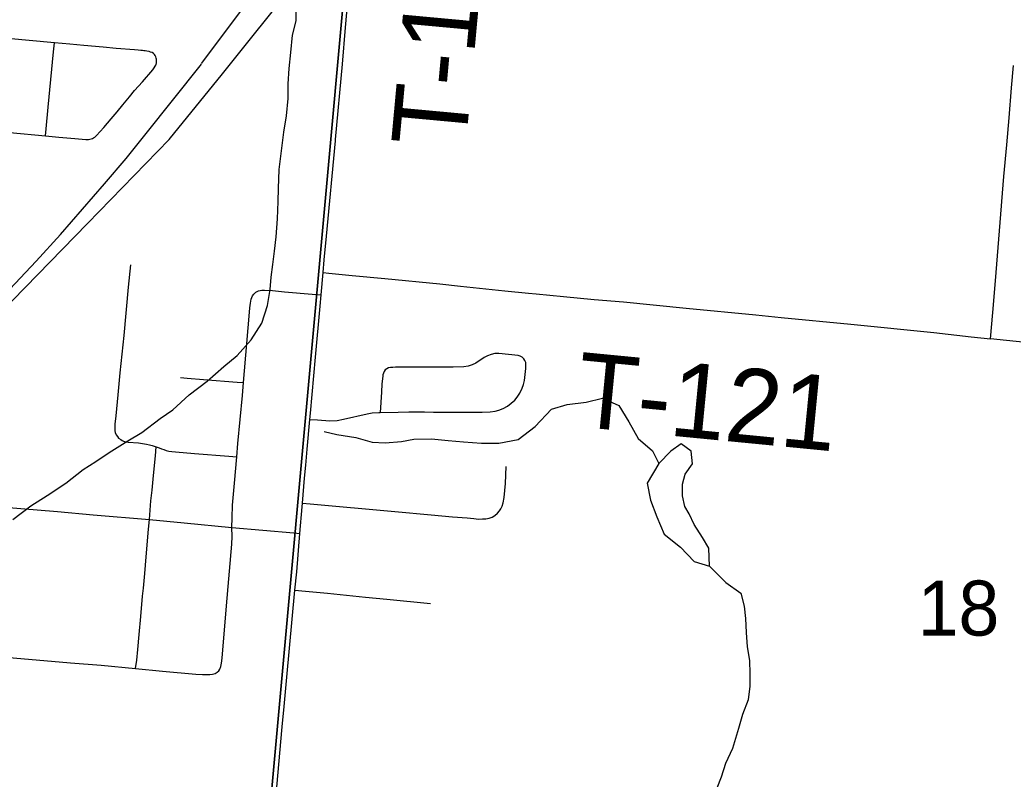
# Model space of a CAD drawing. Extents: x 0 to 1067, y 0 to 440.
# Drawn here: x 802.528 to 803.284, y 352.724 to 353.302 of the extents above; entities that cross this region are included whole.
import ezdxf

# ---------------------------------------------------------------- set-up
doc = ezdxf.new("R2010")
doc.units = 0
for name, color, linetype in [('GM_X_City_Street', 7, 'Continuous'), ('GM_X_Minor_Lake', 7, 'Continuous'), ('GM_X_Minor_River', 7, 'Continuous'), ('GM_X_Rail_Line', 7, 'Continuous'), ('GM_X_Section', 7, 'Continuous'), ('GM_X_Section_Text', 7, 'Continuous'), ('GM_X_Township_Road', 7, 'Continuous'), ('GM_X_Township_Road_Text', 7, 'Continuous')]:
    doc.layers.add(name, color=color, linetype=linetype)

msp = doc.modelspace()

# ---------------------------------------------------------------- linework, layer by layer
at = {"layer": 'GM_X_City_Street'}
for points in [[(802.49288, 353.21865), (802.54739, 353.21361), (802.55772, 353.21269), (802.56973, 353.21163), (802.57809, 353.21089), (802.57915, 353.21087), (802.58015, 353.21087), (802.58119, 353.21098), (802.58224, 353.21123), (802.58316, 353.21158), (802.58411, 353.21207), (802.58493, 353.21263), (802.58576, 353.21334), (802.5864, 353.21397), (802.59183, 353.22005), (802.59756, 353.22656), (802.60194, 353.23187), (802.60631, 353.23713), (802.61145, 353.24331), (802.61534, 353.24812), (802.62121, 353.25481), (802.62921, 353.26394), (802.63024, 353.26545), (802.63101, 353.26666), (802.63137, 353.26732), (802.63161, 353.26792), (802.6319, 353.26919), (802.63202, 353.27026), (802.63201, 353.27133), (802.63193, 353.27207), (802.63177, 353.27284), (802.6315, 353.27379), (802.63107, 353.27471), (802.63052, 353.27554), (802.62963, 353.27633), (802.62858, 353.27695), (802.62754, 353.27738), (802.62637, 353.27771), (802.62471, 353.27808), (802.62347, 353.2783), (802.62243, 353.27843), (802.6214, 353.27857), (802.62, 353.2787), (802.61802, 353.27886), (802.61527, 353.27908), (802.60137, 353.28023), (802.59148, 353.2811), (802.5766, 353.28241), (802.5661, 353.28333), (802.55427, 353.28439), (802.51845, 353.28759)], [(802.54739, 353.21361), (802.54788, 353.21889), (802.54944, 353.23552), (802.55349, 353.27746), (802.55427, 353.28439)], [(802.61215, 353.11542), (802.61053, 353.09856), (802.60699, 353.0616), (802.60409, 353.03321), (802.60256, 353.0165), (802.60095, 353.00048), (802.60035, 352.99415), (802.6002, 352.9918), (802.6002, 352.99014), (802.60027, 352.989), (802.6005, 352.98779), (802.60118, 352.98612), (802.60218, 352.98468), (802.60312, 352.98362), (802.60472, 352.9824), (802.6058, 352.98174), (802.60693, 352.98121), (802.60837, 352.98083), (802.61033, 352.98053), (802.6182, 352.97992), (802.62131, 352.97947), (802.62433, 352.97894), (802.62668, 352.97841), (802.62865, 352.97788), (802.6318, 352.97693), (802.63394, 352.97621), (802.63591, 352.97546), (802.63765, 352.97478), (802.63939, 352.97417), (802.64125, 352.97367), (802.64363, 352.97334), (802.64635, 352.97311), (802.6608, 352.9719), (802.68705, 352.96971), (802.69308, 352.9692)], [(802.67809, 352.80532), (802.67932, 352.80641), (802.68019, 352.80778), (802.68095, 352.80966), (802.68148, 352.8122), (802.68195, 352.81594), (802.6854, 352.85588), (802.68928, 352.90292), (802.68955, 352.90879), (802.68942, 352.91548), (802.68955, 352.92299), (802.68994, 352.93261), (802.69129, 352.94926), (802.69308, 352.9692), (802.694, 352.97953), (802.69739, 353.01605), (802.69823, 353.02588), (802.70252, 353.07629), (802.70312, 353.08283), (802.70361, 353.08639), (802.70416, 353.0894), (802.70509, 353.09186), (802.70605, 353.09317), (802.70771, 353.09471), (802.70976, 353.09567), (802.71207, 353.09605), (802.7143, 353.09618), (802.7204, 353.09587), (802.72945, 353.09496), (802.75049, 353.09321), (802.75738, 353.09273)], [(802.74875, 352.99781), (802.75469, 352.99738), (802.76405, 352.9967), (802.76946, 352.99696), (802.77426, 352.9979), (802.79244, 353.00209), (802.79616, 353.00271), (802.80116, 353.00306), (802.80226, 353.00307), (802.8161, 353.00325), (802.82415, 353.00355), (802.83599, 353.00355), (802.8428, 353.00332), (802.88001, 353.00326), (802.88614, 353.00352), (802.88972, 353.00405), (802.89261, 353.00483), (802.89596, 353.00617), (802.89911, 353.0079), (802.90201, 353.01005), (802.90468, 353.0125), (802.9066, 353.01477), (802.90858, 353.01779), (802.91048, 353.02157), (802.91149, 353.02438), (802.91215, 353.0273), (802.91316, 353.03647), (802.91329, 353.03946), (802.91307, 353.04113), (802.9125, 353.04266), (802.91158, 353.04398), (802.91035, 353.04507), (802.90891, 353.0459), (802.90732, 353.04637), (802.90002, 353.04729), (802.89266, 353.04794), (802.88968, 353.04786), (802.88681, 353.04731), (802.88404, 353.04628), (802.88143, 353.04484), (802.87522, 353.04067), (802.87231, 353.03925), (802.86922, 353.03827), (802.86604, 353.03777), (802.85788, 353.03751), (802.83925, 353.03764), (802.82999, 353.03758), (802.81942, 353.03752), (802.81391, 353.03745), (802.81204, 353.03734), (802.81012, 353.03725), (802.80869, 353.03696), (802.80725, 353.03629), (802.8062, 353.03552), (802.80524, 353.03428), (802.80476, 353.03304), (802.80441, 353.03171), (802.80429, 353.03083), (802.80359, 353.02479), (802.80321, 353.01859), (802.80226, 353.00307)], [(802.65015, 353.02958), (802.65533, 353.02922), (802.66766, 353.02821), (802.69332, 353.02625), (802.69823, 353.02588)], [(802.6161, 352.80812), (802.61689, 352.81451), (802.61766, 352.82262), (802.61882, 352.83414), (802.6201, 352.84771), (802.62144, 352.86333), (802.62199, 352.86936), (802.62301, 352.88044), (802.62408, 352.8933), (802.62597, 352.91431), (802.62653, 352.9215), (802.62719, 352.92863), (802.62773, 352.9358), (802.62858, 352.94389), (802.6295, 352.95223), (802.63049, 352.96274), (802.63118, 352.97013), (802.6318, 352.97693)], [(802.7431, 352.93396), (802.74909, 352.93342), (802.81334, 352.9276), (802.8412, 352.9252), (802.8573, 352.9237), (802.86846, 352.92279), (802.87347, 352.9223), (802.87704, 352.92193), (802.88026, 352.92199), (802.88271, 352.92212), (802.88514, 352.9226), (802.88745, 352.92348), (802.88959, 352.92475), (802.89149, 352.92635), (802.89312, 352.92822), (802.89417, 352.92977), (802.89523, 352.93166), (802.89597, 352.93417), (802.89662, 352.93845), (802.89759, 352.94897), (802.8983, 352.96198)], [(802.47619, 352.93422), (802.5005, 352.93214), (802.5566, 352.92763), (802.58364, 352.92526), (802.62653, 352.9215)], [(802.62653, 352.9215), (802.65311, 352.91917), (802.68942, 352.91548)], [(802.68942, 352.91548), (802.73652, 352.91139), (802.74116, 352.91099)], [(802.73739, 352.86781), (802.74543, 352.86704), (802.76213, 352.86545), (802.79119, 352.86255), (802.80728, 352.86096), (802.84071, 352.85769)], [(802.44711, 352.82277), (802.45292, 352.82227), (802.47893, 352.82006), (802.5664, 352.81247), (802.58989, 352.81065), (802.6161, 352.80812), (802.63661, 352.80614), (802.66205, 352.80392), (802.66701, 352.80366), (802.67255, 352.80375), (802.67454, 352.80396), (802.67672, 352.8045), (802.67809, 352.80532)]]:
    msp.add_lwpolyline(points, dxfattribs=at)
at = {"layer": 'GM_X_Minor_Lake'}
for points in [[(803.05313, 352.8862), (803.05244, 352.8999), (803.04759, 352.9079), (803.04124, 352.91781), (803.03752, 352.9258), (803.03416, 352.93152), (803.03234, 352.9395), (803.03241, 352.94859), (803.03437, 352.95616), (803.04011, 352.96408), (803.03905, 352.97357), (803.03153, 352.97931), (803.02354, 352.97369), (803.01438, 352.96428)], [(803.01438, 352.96428), (803.00556, 352.94918), (803.0081, 352.93627), (803.01291, 352.92372), (803.01848, 352.91041), (803.03088, 352.90045), (803.04139, 352.88975), (803.05313, 352.8862)]]:
    msp.add_lwpolyline(points, dxfattribs=at)
at = {"layer": 'GM_X_Minor_River'}
for points in [[(802.52257, 352.92152), (802.53628, 352.93203), (802.54882, 352.93989), (802.5629, 352.94926), (802.57623, 352.95977), (802.58574, 352.96576), (802.59601, 352.9725), (802.61008, 352.98149), (802.62073, 352.98786), (802.63481, 352.99836), (802.64432, 353.00511), (802.6569, 353.01639), (802.67061, 353.02689), (802.68319, 353.03817), (802.69347, 353.04643), (802.70416, 353.05848), (802.71221, 353.07093), (802.71649, 353.08455), (802.71847, 353.09666), (802.71931, 353.10613), (802.72052, 353.1156), (802.72174, 353.12583), (802.72297, 353.13682), (802.72422, 353.15046), (802.7247, 353.16372), (802.72478, 353.17358), (802.72528, 353.18799), (802.72892, 353.21639), (802.73091, 353.22889), (802.73216, 353.24215), (802.73225, 353.25315), (802.7331, 353.26489), (802.73434, 353.27702), (802.73558, 353.29028), (802.73832, 353.30125), (802.73805, 353.31452)], [(802.75958, 352.98866), (802.7694, 352.98631), (802.78376, 352.98392), (802.79622, 352.98041), (802.80605, 352.97995), (802.81854, 352.98099), (802.82801, 352.98281), (802.84126, 352.98309), (802.85411, 352.98185), (802.86583, 352.98062), (802.87944, 352.97975), (802.89268, 352.97965), (802.90746, 352.98257), (802.92041, 352.99232), (802.93262, 353.00549), (802.94476, 353.00919), (802.95915, 353.01097), (802.97166, 353.01391), (802.9841, 353.0085), (802.99156, 352.99593), (802.99865, 352.98336), (803.00954, 352.9738), (803.01438, 352.96428), (803.00556, 352.94918), (803.0081, 352.93627), (803.01291, 352.92372), (803.01848, 352.91041), (803.03088, 352.90045), (803.04139, 352.88975), (803.05313, 352.8862), (803.06547, 352.87364), (803.07675, 352.86559), (803.07932, 352.85571), (803.08038, 352.84622), (803.08104, 352.8356), (803.08171, 352.8246), (803.08352, 352.81435), (803.08381, 352.80411), (803.08373, 352.79463), (803.08251, 352.7844), (803.07826, 352.77306), (803.07515, 352.76247), (803.07048, 352.74734), (803.06509, 352.73601), (803.06198, 352.72541), (803.0558, 352.70992)]]:
    msp.add_lwpolyline(points, dxfattribs=at)
at = {"layer": 'GM_X_Rail_Line'}
for points in [[(802.66613, 353.26867), (802.69701, 353.30959), (802.73077, 353.36376), (802.81216, 353.48751), (802.85655, 353.56684), (802.89777, 353.64723), (802.96012, 353.76887), (803.20109, 354.23955), (803.47541, 354.77047), (803.5751, 354.97332), (803.62551, 355.07064), (803.67263, 355.14555), (803.72511, 355.22263), (803.77231, 355.28745), (803.82207, 355.35649), (804.04474, 355.62305), (804.29457, 355.92116), (804.76309, 356.47016), (804.84013, 356.56236)], [(802.34777, 352.90839), (802.39459, 352.9594), (802.44632, 353.01049), (802.57936, 353.14691), (802.64164, 353.21072), (802.68216, 353.26073), (802.73937, 353.33239)], [(802.34779, 352.92161), (802.36963, 352.94373), (802.40011, 352.97467), (802.44582, 353.02086), (802.48341, 353.05911), (802.51622, 353.09253), (802.54049, 353.11826), (802.5589, 353.1386), (802.59233, 353.17713), (802.60879, 353.19635), (802.62321, 353.21425), (802.66636, 353.26813)]]:
    msp.add_lwpolyline(points, dxfattribs=at)
at = {"layer": 'GM_X_Section'}
for points in [[(801.74318, 353.49934), (802.78288, 353.41246), (802.69313, 352.42359), (801.6612, 352.51006)], [(803.80305, 353.31387), (803.69832, 352.31199), (802.69313, 352.42359), (802.78288, 353.41246)]]:
    msp.add_lwpolyline(points, close=True, dxfattribs=at)
at = {"layer": 'GM_X_Township_Road'}
for p, q in [((802.75738, 353.09273), (802.75889, 353.10962)), ((802.92105, 353.09332), (802.9419, 353.0913))]:
    msp.add_line(p, q, dxfattribs=at)
for points in [[(802.76815, 353.20974), (802.76824, 353.21074), (802.77349, 353.26815), (802.77581, 353.296), (802.77847, 353.32504), (802.78006, 353.34044)], [(803.26687, 353.05923), (803.2687, 353.07926), (803.27007, 353.09416), (803.2713, 353.10964), (803.27378, 353.14122), (803.27717, 353.18268), (803.27933, 353.2068), (803.28112, 353.22722), (803.28301, 353.25011), (803.28443, 353.26713)], [(802.75889, 353.10962), (802.75976, 353.11935), (802.76141, 353.13727), (802.76815, 353.20974)], [(802.75889, 353.10962), (802.76322, 353.10917), (802.78096, 353.10736), (802.80576, 353.10501), (802.8477, 353.10089), (802.86353, 353.0993), (802.87797, 353.09776), (802.89717, 353.09576), (802.91509, 353.0939), (802.92105, 353.09332)], [(802.74875, 352.99781), (802.74916, 353.00244), (802.75299, 353.04514), (802.75661, 353.0841), (802.75738, 353.09273)], [(802.9419, 353.0913), (802.96521, 353.08918), (802.98748, 353.08718), (803.03526, 353.08251), (803.08833, 353.07733), (803.10749, 353.0753), (803.1607, 353.07027), (803.22378, 353.06386), (803.25218, 353.06055), (803.26687, 353.05923)], [(803.48641, 353.03728), (803.46173, 353.0396), (803.4364, 353.04202), (803.41109, 353.04456), (803.37035, 353.04881), (803.31977, 353.05385), (803.29881, 353.05594), (803.26687, 353.05923)], [(802.7431, 352.93396), (802.74472, 352.95297), (802.74566, 352.96285), (802.74669, 352.97524), (802.74875, 352.99781)], [(802.74116, 352.91099), (802.74287, 352.93131), (802.7431, 352.93396)], [(802.73739, 352.86781), (802.73871, 352.88181), (802.74116, 352.91099)], [(802.72135, 352.69199), (802.72774, 352.76388), (802.7292, 352.77933), (802.73115, 352.8016), (802.73739, 352.86781)]]:
    msp.add_lwpolyline(points, dxfattribs=at)

# ---------------------------------------------------------------- texts
at = {"layer": 'GM_X_Section_Text'}
msp.add_text('18', height=0.041856, rotation=0.00001, dxfattribs=at).set_placement((803.21144, 352.83325))
at = {"layer": 'GM_X_Township_Road_Text'}
for s, rotation, p in [('T-126', 84.72983, (802.86724, 353.20354)), ('T-121', 354.46528, (802.94987, 352.99257))]:
    msp.add_text(s, height=0.056818, rotation=rotation, dxfattribs=at).set_placement(p)

doc.saveas('drawing.dxf')
